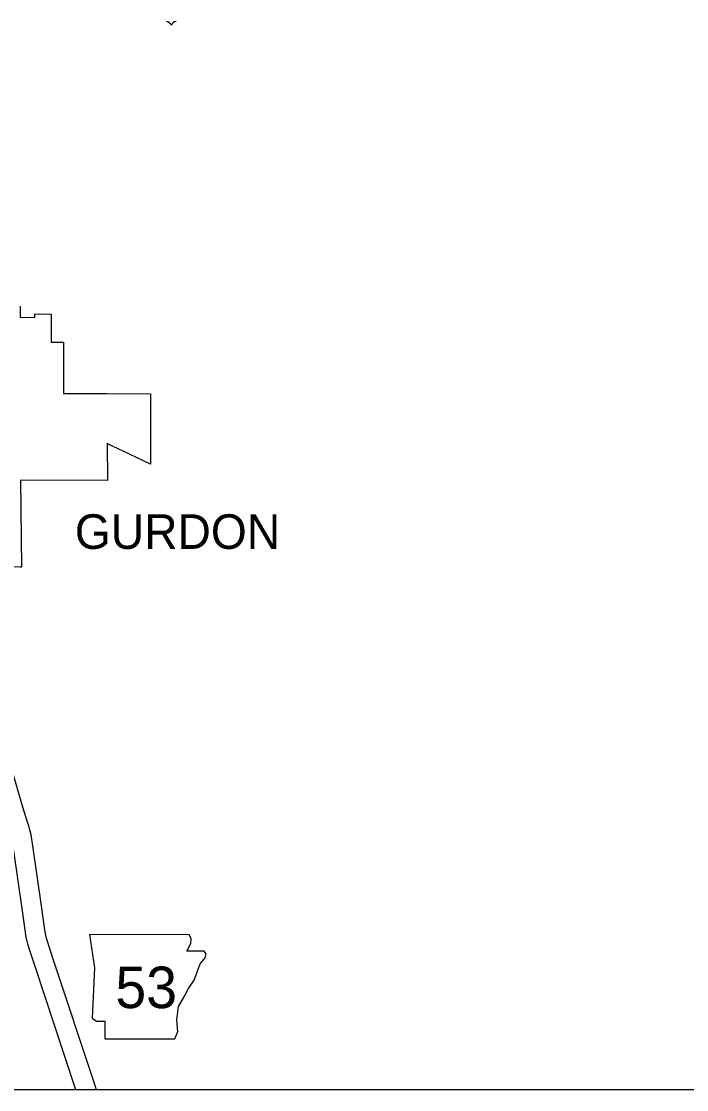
# Model space of a CAD drawing. Extents: x 1369979 to 1371646, y 379997 to 381064.
# Drawn here: x 1370321.9 to 1370401.3, y 380650.5 to 380778 of the extents above; entities that cross this region are included whole.
import ezdxf

# ---------------------------------------------------------------- set-up
doc = ezdxf.new("R2010")
doc.units = 0
doc.layers.add('R_Border Notes', color=7, linetype='Continuous')
doc.layers.add('R_No Plot', color=7, linetype='Continuous')

msp = doc.modelspace()

# ---------------------------------------------------------------- linework, layer by layer
at = {"layer": 'R_Border Notes'}
for points in [[(1370321.76, 380744.02), (1370321.76, 380742.7), (1370323.5, 380742.67), (1370323.52, 380743.08), (1370325.46, 380743.05), (1370325.46, 380739.73), (1370326.94, 380739.71), (1370326.92, 380733.6), (1370332.11, 380733.57), (1370337.3, 380733.53), (1370337.33, 380725.15), (1370334.82, 380726.35), (1370332.77, 380727.31), (1370332.15, 380727.61), (1370332.17, 380723.22), (1370321.79, 380723.26), (1370321.92, 380712.88), (1370321.77, 380712.88), (1370312.07, 380713.17), (1370309.81, 380718.41), (1370300.84, 380718.67), (1370300.81, 380723.84)], [(1370324.34, 380672.2), (1370323.27, 380679.63), (1370323.07, 380680.93), (1370322.92, 380681.55), (1370322.78, 380682.01), (1370322.57, 380682.55), (1370321.94, 380684.63), (1370319.64, 380692.64)], [(1370322.02, 380671.87), (1370320.95, 380679.29)], [(1370328.4, 380650.53), (1370328.33, 380650.76), (1370323.53, 380665.23), (1370322.81, 380667.39), (1370322.62, 380668.04), (1370322.47, 380668.72), (1370322.35, 380669.56), (1370322.02, 380671.87)], [(1370330.87, 380650.53), (1370330.56, 380651.49), (1370325.75, 380665.98), (1370325.05, 380668.07), (1370324.9, 380668.61), (1370324.78, 380669.14), (1370324.67, 380669.89), (1370324.34, 380672.2)]]:
    msp.add_lwpolyline(points, dxfattribs=at)
msp.add_lwpolyline([(1370330.02, 380669.03), (1370330.61, 380665.07), (1370330.35, 380659.05), (1370330.88, 380658.72), (1370331.87, 380658.72), (1370331.87, 380656.61), (1370340.2, 380656.61), (1370340.59, 380657.47), (1370340.46, 380658.85), (1370340.66, 380660.44), (1370341.39, 380661.69), (1370341.85, 380662.62), (1370342.51, 380663.61), (1370342.91, 380664.67), (1370343.24, 380665.53), (1370343.83, 380666.25), (1370343.96, 380666.72), (1370343.7, 380667.05), (1370341.65, 380667.05), (1370342.11, 380667.97), (1370342.18, 380668.57), (1370341.91, 380669.02)], close=True, dxfattribs=at)
for centre, start, end in [((1370338.94, 380777.06), 28.0342, 72.9864), ((1370340.65, 380777.06), 107.0136, 151.9658)]:
    msp.add_arc(centre, 0.968, start, end, dxfattribs=at)
at = {"layer": 'R_No Plot'}
msp.add_lwpolyline([(1370052.8, 381020.95), (1370474.58, 381020.95), (1370474.58, 380650.53), (1370052.8, 380650.53)], close=True, dxfattribs=at)

# ---------------------------------------------------------------- texts
at = {"layer": 'R_Border Notes'}
for s, height, p in [('GURDON', 4.125, (1370328.28, 380715.05)), ('53', 4.95, (1370333.12, 380660.26))]:
    msp.add_text(s, height=height, dxfattribs=at).set_placement(p)

doc.saveas('drawing.dxf')
